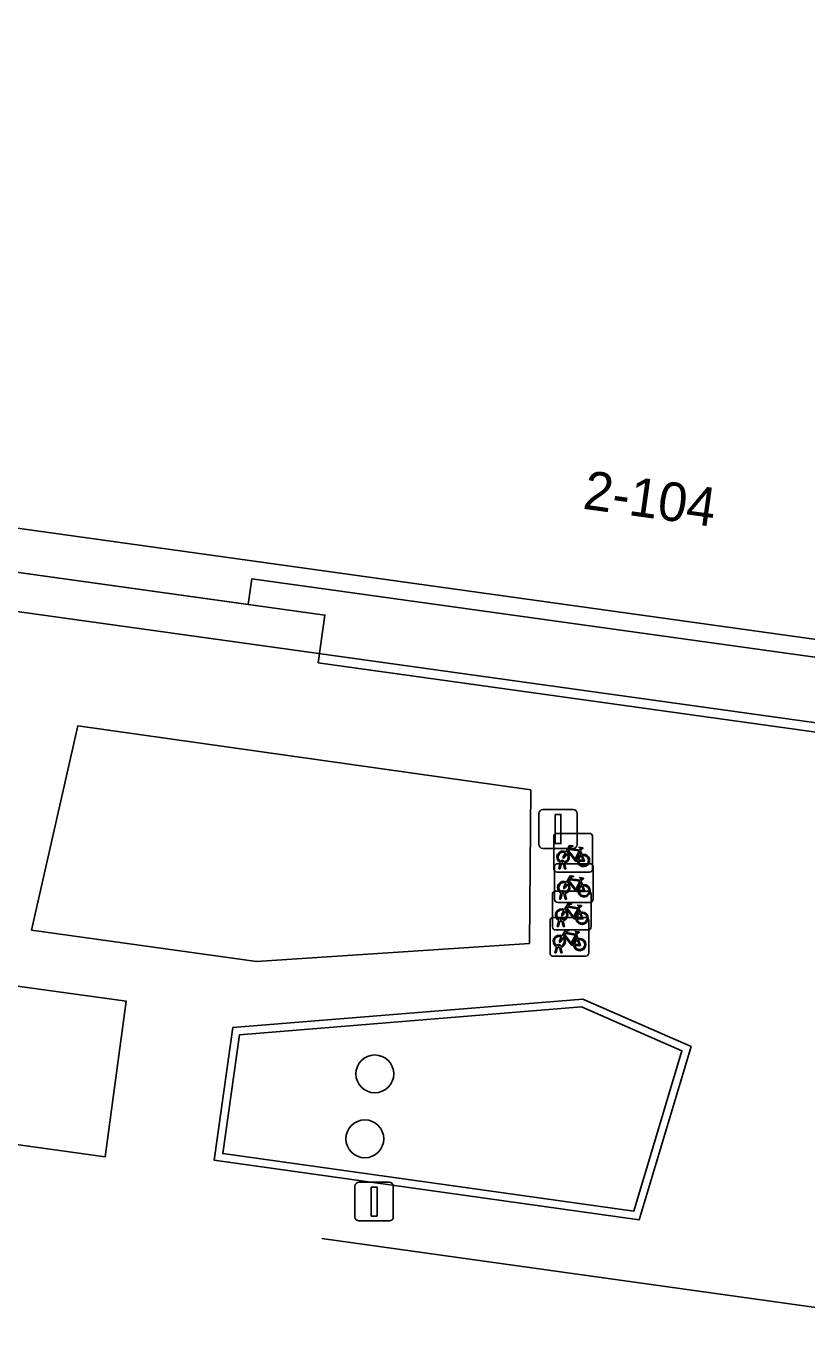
# Model space of a CAD drawing. Extents: x 155640 to 156811, y 382821 to 384049.
# Drawn here: x 156457.59 to 156477.74, y 383662.57 to 383696.55 of the extents above; entities that cross this region are included whole.
import ezdxf

# ---------------------------------------------------------------- set-up
doc = ezdxf.new("R2010")
doc.units = 0
for name, color, linetype in [('IMGEO_Boom', 7, 'Continuous'), ('IMGEO_Fietsenrek', 7, 'Continuous'), ('IMGEO_Groenvoorziening', 7, 'Continuous'), ('IMGEO_Lichtmast', 7, 'Continuous'), ('IMGEO_Lijnafwatering', 7, 'Continuous'), ('IMGEO_Muur', 7, 'Continuous'), ('IMGEO_Pand', 7, 'Continuous'), ('IMGEO_Pand_nummerreeks', 7, 'Continuous'), ('IMGEO_Pand_overbouw', 7, 'Continuous'), ('IMGEO_Rijbaan_lokaal_gesloten', 7, 'Continuous'), ('IMGEO_Voetgangersgebied_open', 7, 'Continuous'), ('IMGEO_Voetpad_open', 7, 'Continuous')]:
    doc.layers.add(name, color=color, linetype=linetype)

msp = doc.modelspace()

# ---------------------------------------------------------------- linework, layer by layer
at = {"layer": 'IMGEO_Boom'}
for centre in [(156466.588, 383669.469), (156466.331, 383667.79)]:
    msp.add_circle(centre, 0.489, dxfattribs=at)
at = {"layer": 'IMGEO_Fietsenrek'}
for p, q in [((156471.212, 383674.761), (156471.212, 383675.602)), ((156471.212, 383675.602), (156471.212, 383674.761)), ((156471.287, 383675.686), (156472.128, 383675.686)), ((156472.128, 383675.686), (156471.287, 383675.686)), ((156472.212, 383675.611), (156472.212, 383674.77)), ((156472.212, 383674.77), (156472.212, 383675.611)), ((156471.899, 383675.235), (156471.935, 383675.14)), ((156471.303, 383674.902), (156472.144, 383674.902)), ((156472.144, 383674.902), (156471.303, 383674.902)), ((156471.339, 383674.77), (156471.378, 383674.93)), ((156471.408, 383674.918), (156471.373, 383674.77)), ((156471.45, 383674.942), (156471.449, 383674.946)), ((156471.491, 383674.77), (156471.457, 383674.912)), ((156471.481, 383674.953), (156471.482, 383674.946)), ((156471.489, 383674.916), (156471.524, 383674.77)), ((156471.228, 383673.977), (156471.228, 383674.818)), ((156471.228, 383674.818), (156471.228, 383673.977)), ((156472.137, 383674.686), (156471.296, 383674.686)), ((156471.296, 383674.686), (156472.137, 383674.686)), ((156471.373, 383674.77), (156471.339, 383674.77)), ((156471.524, 383674.77), (156471.491, 383674.77)), ((156472.228, 383674.827), (156472.228, 383673.986)), ((156472.228, 383673.986), (156472.228, 383674.827)), ((156471.25, 383674.192), (156472.091, 383674.192)), ((156472.091, 383674.192), (156471.25, 383674.192)), ((156471.915, 383674.451), (156471.951, 383674.356)), ((156471.175, 383673.267), (156471.175, 383674.108)), ((156471.175, 383674.108), (156471.175, 383673.267)), ((156472.153, 383673.902), (156471.312, 383673.902)), ((156471.312, 383673.902), (156472.153, 383673.902)), ((156471.355, 383673.986), (156471.394, 383674.146)), ((156471.389, 383673.986), (156471.355, 383673.986)), ((156471.424, 383674.134), (156471.389, 383673.986)), ((156471.466, 383674.158), (156471.465, 383674.162)), ((156471.507, 383673.986), (156471.473, 383674.128)), ((156471.497, 383674.169), (156471.498, 383674.162)), ((156471.505, 383674.132), (156471.54, 383673.986)), ((156471.54, 383673.986), (156471.507, 383673.986)), ((156472.175, 383674.117), (156472.175, 383673.276)), ((156472.175, 383673.276), (156472.175, 383674.117)), ((156471.189, 383673.51), (156472.03, 383673.51)), ((156472.03, 383673.51), (156471.189, 383673.51)), ((156471.862, 383673.741), (156471.898, 383673.646)), ((156471.114, 383672.585), (156471.114, 383673.426)), ((156471.114, 383673.426), (156471.114, 383672.585)), ((156472.1, 383673.192), (156471.259, 383673.192)), ((156471.259, 383673.192), (156472.1, 383673.192)), ((156471.302, 383673.276), (156471.341, 383673.436)), ((156471.336, 383673.276), (156471.302, 383673.276)), ((156471.371, 383673.424), (156471.336, 383673.276)), ((156471.413, 383673.448), (156471.412, 383673.452)), ((156471.454, 383673.276), (156471.42, 383673.418)), ((156471.444, 383673.459), (156471.445, 383673.452)), ((156471.452, 383673.422), (156471.487, 383673.276)), ((156471.487, 383673.276), (156471.454, 383673.276)), ((156472.114, 383673.435), (156472.114, 383672.594)), ((156472.114, 383672.594), (156472.114, 383673.435)), ((156471.801, 383673.059), (156471.837, 383672.964)), ((156472.039, 383672.51), (156471.198, 383672.51)), ((156471.198, 383672.51), (156472.039, 383672.51)), ((156471.241, 383672.594), (156471.28, 383672.754)), ((156471.275, 383672.594), (156471.241, 383672.594)), ((156471.31, 383672.742), (156471.275, 383672.594)), ((156471.352, 383672.766), (156471.351, 383672.77)), ((156471.393, 383672.594), (156471.359, 383672.736)), ((156471.383, 383672.777), (156471.384, 383672.77)), ((156471.391, 383672.74), (156471.426, 383672.594)), ((156471.426, 383672.594), (156471.393, 383672.594))]:
    msp.add_line(p, q, dxfattribs=at)
for points in [[(156471.525, 383675.212), (156471.62, 383675.376), (156471.706, 383675.362), (156471.708, 383675.353), (156471.652, 383675.342), (156471.625, 383675.297), (156471.881, 383675.256)], [(156471.821, 383674.968), (156471.771, 383674.968), (156471.58, 383675.219), (156471.561, 383675.187)], [(156471.868, 383675.231), (156471.611, 383675.272), (156471.594, 383675.243), (156471.761, 383675.023), (156471.868, 383675.231)], [(156471.916, 383675.133), (156471.886, 383675.21), (156471.777, 383674.992), (156471.82, 383674.992)], [(156471.881, 383675.256), (156471.906, 383675.305), (156471.9, 383675.309), (156471.877, 383675.313), (156471.865, 383675.32), (156471.864, 383675.323), (156471.866, 383675.328), (156471.961, 383675.313), (156471.963, 383675.303), (156471.953, 383675.29), (156471.941, 383675.284), (156471.927, 383675.29), (156471.899, 383675.235)], [(156471.546, 383675.16), (156471.494, 383675.07), (156471.454, 383675.045), (156471.455, 383675.092), (156471.51, 383675.186)], [(156471.85, 383674.992), (156471.97, 383674.991), (156471.926, 383675.105)], [(156471.946, 383675.112), (156472.001, 383674.967), (156471.851, 383674.967)], [(156471.541, 383674.428), (156471.636, 383674.592), (156471.722, 383674.578), (156471.724, 383674.569), (156471.668, 383674.558), (156471.641, 383674.513), (156471.897, 383674.472)], [(156471.897, 383674.472), (156471.922, 383674.521), (156471.916, 383674.525), (156471.893, 383674.529), (156471.881, 383674.536), (156471.88, 383674.539), (156471.882, 383674.544), (156471.977, 383674.529), (156471.979, 383674.519), (156471.969, 383674.506), (156471.957, 383674.5), (156471.943, 383674.506), (156471.915, 383674.451)], [(156471.562, 383674.376), (156471.51, 383674.286), (156471.47, 383674.261), (156471.471, 383674.308), (156471.526, 383674.402)], [(156471.837, 383674.184), (156471.787, 383674.184), (156471.596, 383674.435), (156471.577, 383674.403)], [(156471.884, 383674.447), (156471.627, 383674.488), (156471.61, 383674.459), (156471.777, 383674.239), (156471.884, 383674.447)], [(156471.932, 383674.349), (156471.902, 383674.426), (156471.793, 383674.208), (156471.836, 383674.208)], [(156471.866, 383674.208), (156471.986, 383674.207), (156471.942, 383674.321)], [(156471.962, 383674.328), (156472.017, 383674.183), (156471.867, 383674.183)], [(156471.488, 383673.718), (156471.583, 383673.882), (156471.669, 383673.868), (156471.671, 383673.859), (156471.615, 383673.848), (156471.588, 383673.803), (156471.844, 383673.762)], [(156471.509, 383673.666), (156471.457, 383673.576), (156471.417, 383673.551), (156471.418, 383673.598), (156471.473, 383673.692)], [(156471.784, 383673.474), (156471.734, 383673.474), (156471.543, 383673.725), (156471.524, 383673.693)], [(156471.831, 383673.737), (156471.574, 383673.778), (156471.557, 383673.749), (156471.724, 383673.529), (156471.831, 383673.737)], [(156471.879, 383673.639), (156471.849, 383673.716), (156471.74, 383673.498), (156471.783, 383673.498)], [(156471.813, 383673.498), (156471.933, 383673.497), (156471.889, 383673.611)], [(156471.909, 383673.618), (156471.964, 383673.473), (156471.814, 383673.473)], [(156471.844, 383673.762), (156471.869, 383673.811), (156471.863, 383673.815), (156471.84, 383673.819), (156471.828, 383673.826), (156471.827, 383673.829), (156471.829, 383673.834), (156471.924, 383673.819), (156471.926, 383673.809), (156471.916, 383673.796), (156471.904, 383673.79), (156471.89, 383673.796), (156471.862, 383673.741)], [(156471.427, 383673.036), (156471.522, 383673.2), (156471.608, 383673.186), (156471.61, 383673.177), (156471.554, 383673.166), (156471.527, 383673.121), (156471.783, 383673.08)], [(156471.448, 383672.984), (156471.396, 383672.894), (156471.356, 383672.869), (156471.357, 383672.916), (156471.412, 383673.01)], [(156471.723, 383672.792), (156471.673, 383672.792), (156471.482, 383673.043), (156471.463, 383673.011)], [(156471.77, 383673.055), (156471.513, 383673.096), (156471.496, 383673.067), (156471.663, 383672.847), (156471.77, 383673.055)], [(156471.818, 383672.957), (156471.788, 383673.034), (156471.679, 383672.816), (156471.722, 383672.816)], [(156471.752, 383672.816), (156471.872, 383672.815), (156471.828, 383672.929)], [(156471.848, 383672.936), (156471.903, 383672.791), (156471.753, 383672.791)], [(156471.783, 383673.08), (156471.808, 383673.129), (156471.802, 383673.133), (156471.779, 383673.137), (156471.767, 383673.144), (156471.766, 383673.147), (156471.768, 383673.152), (156471.863, 383673.137), (156471.865, 383673.127), (156471.855, 383673.114), (156471.843, 383673.108), (156471.829, 383673.114), (156471.801, 383673.059)]]:
    msp.add_lwpolyline(points, dxfattribs=at)
for centre, radius, start, end in [((156471.29, 383675.608), 0.0779, 92.4484, 184.2845), ((156471.29, 383675.608), 0.0779, 92.4484, 184.2845), ((156472.134, 383675.608), 0.0779, 2.4484, 94.2845), ((156472.134, 383675.608), 0.0779, 2.4484, 94.2845), ((156471.452, 383675.071), 0.159, 62.6766, 242.1369), ((156471.452, 383675.071), 0.129, 63.3192, 238.903), ((156471.306, 383674.824), 0.0779, 92.4484, 184.2845), ((156471.306, 383674.824), 0.0779, 92.4484, 184.2845), ((156471.432, 383674.942), 0.0499, 12.8025, 158.6934), ((156471.452, 383675.071), 0.159, 253.9967, 271.7867), ((156471.432, 383674.942), 0.0174, 12.8025, 163.4502), ((156471.452, 383675.071), 0.129, 253.415, 269.0204), ((156471.452, 383675.071), 0.129, 283.6043, 43.4302), ((156471.452, 383675.071), 0.159, 283.5766, 46.6042), ((156471.979, 383674.987), 0.159, 113.3408, 178.3217), ((156471.979, 383674.987), 0.159, 187.0065, 105.7708), ((156471.979, 383674.987), 0.129, 113.923, 177.9556), ((156471.979, 383674.987), 0.129, 188.6715, 104.5883), ((156472.15, 383674.824), 0.0779, 2.4484, 94.2845), ((156472.15, 383674.824), 0.0779, 2.4484, 94.2845), ((156471.29, 383674.764), 0.0779, 182.4484, 274.2845), ((156471.29, 383674.764), 0.0779, 182.4484, 274.2845), ((156472.134, 383674.764), 0.0779, 272.4484, 4.2845), ((156472.134, 383674.764), 0.0779, 272.4484, 4.2845), ((156471.253, 383674.114), 0.0779, 92.4484, 184.2845), ((156471.253, 383674.114), 0.0779, 92.4484, 184.2845), ((156471.468, 383674.287), 0.159, 62.6766, 242.1369), ((156471.468, 383674.287), 0.129, 63.3192, 238.903), ((156471.448, 383674.158), 0.0499, 12.8025, 158.6934), ((156471.468, 383674.287), 0.129, 283.6043, 43.4302), ((156471.468, 383674.287), 0.159, 283.5766, 46.6042), ((156471.995, 383674.203), 0.159, 113.3408, 178.3217), ((156471.995, 383674.203), 0.159, 187.0065, 105.7708), ((156471.995, 383674.203), 0.129, 113.923, 177.9556), ((156471.995, 383674.203), 0.129, 188.6715, 104.5883), ((156472.097, 383674.114), 0.0779, 2.4484, 94.2845), ((156472.097, 383674.114), 0.0779, 2.4484, 94.2845), ((156471.306, 383673.98), 0.0779, 182.4484, 274.2845), ((156471.306, 383673.98), 0.0779, 182.4484, 274.2845), ((156471.468, 383674.287), 0.159, 253.9967, 271.7867), ((156471.448, 383674.158), 0.0174, 12.8025, 163.4502), ((156471.468, 383674.287), 0.129, 253.415, 269.0204), ((156472.15, 383673.98), 0.0779, 272.4484, 4.2845), ((156472.15, 383673.98), 0.0779, 272.4484, 4.2845), ((156471.192, 383673.432), 0.0779, 92.4484, 184.2845), ((156471.192, 383673.432), 0.0779, 92.4484, 184.2845), ((156471.415, 383673.577), 0.159, 62.6766, 242.1369), ((156471.415, 383673.577), 0.129, 63.3192, 238.903), ((156471.415, 383673.577), 0.129, 283.6043, 43.4302), ((156471.415, 383673.577), 0.159, 283.5766, 46.6042), ((156471.942, 383673.493), 0.159, 113.3408, 178.3217), ((156471.942, 383673.493), 0.159, 187.0065, 105.7708), ((156471.942, 383673.493), 0.129, 113.923, 177.9556), ((156471.942, 383673.493), 0.129, 188.6715, 104.5883), ((156472.036, 383673.432), 0.0779, 2.4484, 94.2845), ((156472.036, 383673.432), 0.0779, 2.4484, 94.2845), ((156471.253, 383673.27), 0.0779, 182.4484, 274.2845), ((156471.253, 383673.27), 0.0779, 182.4484, 274.2845), ((156471.395, 383673.448), 0.0499, 12.8025, 158.6934), ((156471.415, 383673.577), 0.159, 253.9967, 271.7867), ((156471.395, 383673.448), 0.0174, 12.8025, 163.4502), ((156471.415, 383673.577), 0.129, 253.415, 269.0204), ((156472.097, 383673.27), 0.0779, 272.4484, 4.2845), ((156472.097, 383673.27), 0.0779, 272.4484, 4.2845), ((156471.354, 383672.895), 0.159, 62.6766, 242.1369), ((156471.354, 383672.895), 0.129, 63.3192, 238.903), ((156471.354, 383672.895), 0.129, 283.6043, 43.4302), ((156471.354, 383672.895), 0.159, 283.5766, 46.6042), ((156471.881, 383672.811), 0.159, 113.3408, 178.3217), ((156471.881, 383672.811), 0.159, 187.0065, 105.7708), ((156471.881, 383672.811), 0.129, 113.923, 177.9556), ((156471.881, 383672.811), 0.129, 188.6715, 104.5883), ((156471.192, 383672.588), 0.0779, 182.4484, 274.2845), ((156471.192, 383672.588), 0.0779, 182.4484, 274.2845), ((156471.334, 383672.766), 0.0499, 12.8025, 158.6934), ((156471.354, 383672.895), 0.159, 253.9967, 271.7867), ((156471.334, 383672.766), 0.0174, 12.8025, 163.4502), ((156471.354, 383672.895), 0.129, 253.415, 269.0204), ((156472.036, 383672.588), 0.0779, 272.4484, 4.2845), ((156472.036, 383672.588), 0.0779, 272.4484, 4.2845)]:
    msp.add_arc(centre, radius, start, end, dxfattribs=at)
at = {"layer": 'IMGEO_Groenvoorziening'}
msp.add_lwpolyline([(156470.582, 383672.839), (156470.617, 383676.809), (156458.914, 383678.465), (156457.719, 383673.188), (156463.534, 383672.374)], close=True, dxfattribs=at)
at = {"layer": 'IMGEO_Lichtmast'}
for p, q in [((156470.926, 383676.299), (156471.716, 383676.299)), ((156471.716, 383676.299), (156470.926, 383676.299)), ((156470.826, 383675.399), (156470.826, 383676.199)), ((156470.826, 383676.199), (156470.826, 383675.399)), ((156471.816, 383676.199), (156471.816, 383675.399)), ((156471.816, 383675.399), (156471.816, 383676.199)), ((156471.716, 383675.299), (156470.926, 383675.299)), ((156470.926, 383675.299), (156471.716, 383675.299)), ((156466.076, 383665.767), (156466.076, 383666.567)), ((156466.076, 383666.567), (156466.076, 383665.767)), ((156466.176, 383666.667), (156466.966, 383666.667)), ((156466.966, 383666.667), (156466.176, 383666.667)), ((156467.066, 383666.567), (156467.066, 383665.767)), ((156467.066, 383665.767), (156467.066, 383666.567)), ((156466.966, 383665.667), (156466.176, 383665.667)), ((156466.176, 383665.667), (156466.966, 383665.667))]:
    msp.add_line(p, q, dxfattribs=at)
for points in [[(156471.246, 383676.174), (156471.396, 383676.174), (156471.396, 383675.424), (156471.246, 383675.424), (156471.246, 383676.174)], [(156466.496, 383666.542), (156466.646, 383666.542), (156466.646, 383665.792), (156466.496, 383665.792), (156466.496, 383666.542)]]:
    msp.add_lwpolyline(points, dxfattribs=at)
for centre, start, end in [((156470.926, 383676.199), 90, 180), ((156470.926, 383676.199), 90, 180), ((156471.716, 383676.199), 0, 90), ((156471.716, 383676.199), 360, 90), ((156470.926, 383675.399), 180, 270), ((156470.926, 383675.399), 180, 270), ((156471.716, 383675.399), 270, 0), ((156471.716, 383675.399), 270, 0), ((156466.176, 383666.567), 90, 180), ((156466.176, 383666.567), 90, 180), ((156466.966, 383666.567), 0, 90), ((156466.966, 383666.567), 360, 90), ((156466.176, 383665.767), 180, 270), ((156466.176, 383665.767), 180, 270), ((156466.966, 383665.767), 270, 0), ((156466.966, 383665.767), 270, 0)]:
    msp.add_arc(centre, 0.1, start, end, dxfattribs=at)
at = {"layer": 'IMGEO_Lijnafwatering'}
for points in [[(156476.564, 383678.741), (156456.412, 383681.551)], [(156496.589, 383675.948), (156476.564, 383678.741)], [(156484.148, 383662.571), (156465.222, 383665.209)]]:
    msp.add_lwpolyline(points, dxfattribs=at)
at = {"layer": 'IMGEO_Muur'}
for points in [[(156474.758, 383670.178), (156471.965, 383671.401), (156462.918, 383670.666), (156462.436, 383667.24), (156473.42, 383665.696)], [(156473.278, 383665.918), (156462.662, 383667.41), (156463.094, 383670.48), (156471.931, 383671.198), (156474.516, 383670.066)]]:
    msp.add_lwpolyline(points, close=True, dxfattribs=at)
at = {"layer": 'IMGEO_Pand'}
msp.add_lwpolyline([(156438.014, 383699.718), (156436.208, 383686.52), (156516.68, 383675.304), (156518.313, 383687.13), (156517.212, 383687.287), (156518.219, 383694.329), (156519.308, 383694.178), (156524.529, 383731.715)], dxfattribs=at)
at = {"layer": 'IMGEO_Pand_overbouw'}
msp.add_lwpolyline([(156524.529, 383731.715), (156519.308, 383694.178), (156518.219, 383694.329), (156517.212, 383687.287), (156518.313, 383687.13), (156516.68, 383675.304), (156436.208, 383686.52), (156438.014, 383699.718), (156438.115, 383699.703), (156438.461, 383700.239), (156438.64, 383701.529), (156432.591, 383702.361), (156430.466, 383687.075), (156436.756, 383686.197), (156436.634, 383685.326), (156465.3, 383681.328), (156465.128, 383680.095), (156509.572, 383673.897), (156509.748, 383675.153), (156517.613, 383674.051), (156518.79, 383682.442), (156518.138, 383682.533), (156525.621, 383736.263)], dxfattribs=at)
at = {"layer": 'IMGEO_Rijbaan_lokaal_gesloten'}
for points in [[(156460.164, 383671.351), (156452.294, 383672.435), (156451.743, 383668.422), (156459.621, 383667.327)], [(156474.516, 383670.066), (156471.931, 383671.198), (156463.094, 383670.48), (156462.662, 383667.41), (156473.278, 383665.918)]]:
    msp.add_lwpolyline(points, close=True, dxfattribs=at)
at = {"layer": 'IMGEO_Voetgangersgebied_open'}
msp.add_lwpolyline([(156529.811, 383667.869), (156517.613, 383674.051), (156509.748, 383675.153), (156509.833, 383675.802), (156463.412, 383682.264), (156463.32, 383681.604), (156436.634, 383685.326), (156436.756, 383686.197), (156430.466, 383687.075), (156432.591, 383702.361)], dxfattribs=at)
for points in [[(156470.582, 383672.839), (156463.534, 383672.374), (156457.719, 383673.188), (156458.914, 383678.465), (156470.617, 383676.809)], [(156451.743, 383668.422), (156452.294, 383672.435), (156460.164, 383671.351), (156459.621, 383667.327)], [(156462.436, 383667.24), (156462.918, 383670.666), (156471.965, 383671.401), (156474.758, 383670.178), (156473.42, 383665.696)]]:
    msp.add_lwpolyline(points, close=True, dxfattribs=at)
at = {"layer": 'IMGEO_Voetpad_open'}
msp.add_lwpolyline([(156524.529, 383731.715), (156519.308, 383694.178), (156518.219, 383694.329), (156517.212, 383687.287), (156518.313, 383687.13), (156516.68, 383675.304), (156436.208, 383686.52), (156438.014, 383699.718), (156438.115, 383699.703), (156438.461, 383700.239), (156438.64, 383701.529), (156432.591, 383702.361), (156430.466, 383687.075), (156436.756, 383686.197), (156436.634, 383685.326), (156463.32, 383681.604), (156463.412, 383682.264), (156509.833, 383675.802), (156509.748, 383675.153), (156517.613, 383674.051), (156518.79, 383682.442), (156518.138, 383682.533), (156525.621, 383736.263)], dxfattribs=at)

# ---------------------------------------------------------------- texts
at = {"layer": 'IMGEO_Pand_nummerreeks'}
msp.add_text('2-104', height=1, rotation=352.0358, dxfattribs=at).set_placement((156471.936, 383684.083))

doc.saveas('drawing.dxf')
